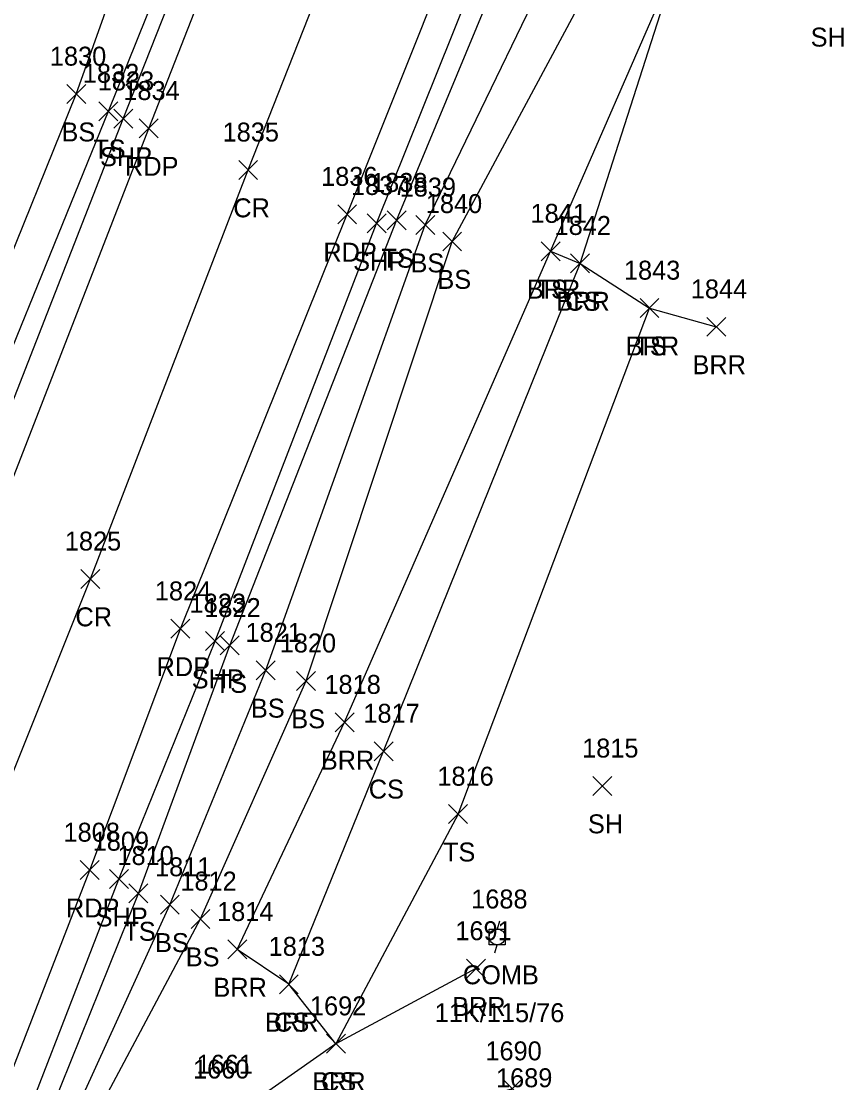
# Model space of a CAD drawing. Extents: x 1554917 to 1555870, y 813367 to 816333.
# Drawn here: x 1555289.9 to 1555376.7, y 814161.6 to 814273.6 of the extents above; entities that cross this region are included whole.
import ezdxf

# ---------------------------------------------------------------- set-up
doc = ezdxf.new("R2010")
doc.units = 0
for name, color, linetype in [('C_I', 7, 'Continuous'), ('L_A', 7, 'Continuous'), ('L_I', 7, 'Continuous'), ('L_TIC', 7, 'Continuous'), ('LABL', 7, 'Continuous'), ('LELB', 7, 'Continuous'), ('P_A', 7, 'Continuous'), ('P_I', 7, 'Continuous'), ('P_TIC', 7, 'Continuous'), ('PET', 7, 'Continuous'), ('PRC', 7, 'Continuous'), ('PSP', 7, 'Continuous'), ('R_I', 7, 'Continuous'), ('U_A', 7, 'Continuous'), ('U_C', 7, 'Continuous'), ('U_I', 7, 'Continuous'), ('UP', 7, 'Continuous')]:
    doc.layers.add(name, color=color, linetype=linetype)

msp = doc.modelspace()

# ---------------------------------------------------------------- linework, layer by layer
at = {"layer": 'L_TIC'}
for points in [[(1555294.68, 814264.95), (1555296.68, 814266.95)], [(1555296.68, 814264.95), (1555294.68, 814266.95)], [(1555298.07, 814263.14), (1555300.07, 814265.14)], [(1555300.07, 814263.14), (1555298.07, 814265.14)], [(1555328.49, 814251.62), (1555330.49, 814253.62)], [(1555330.49, 814251.62), (1555328.49, 814253.62)], [(1555331.52, 814251.13), (1555333.52, 814253.13)], [(1555333.52, 814251.13), (1555331.52, 814253.13)], [(1555334.36, 814249.39), (1555336.36, 814251.39)], [(1555336.36, 814249.39), (1555334.36, 814251.39)], [(1555344.75, 814248.36), (1555346.75, 814250.36)], [(1555346.75, 814248.36), (1555344.75, 814250.36)], [(1555344.75, 814248.36), (1555346.75, 814250.36)], [(1555346.75, 814248.36), (1555344.75, 814250.36)], [(1555347.86, 814247.08), (1555349.86, 814249.08)], [(1555349.86, 814247.08), (1555347.86, 814249.08)], [(1555347.86, 814247.08), (1555349.86, 814249.08)], [(1555349.86, 814247.08), (1555347.86, 814249.08)], [(1555355.19, 814242.36), (1555357.19, 814244.36)], [(1555357.19, 814242.36), (1555355.19, 814244.36)], [(1555355.19, 814242.36), (1555357.19, 814244.36)], [(1555357.19, 814242.36), (1555355.19, 814244.36)], [(1555362.24, 814240.38), (1555364.24, 814242.38)], [(1555364.24, 814240.38), (1555362.24, 814242.38)], [(1555310.89, 814206.75), (1555312.89, 814208.75)], [(1555312.89, 814206.75), (1555310.89, 814208.75)], [(1555314.68, 814204.13), (1555316.68, 814206.13)], [(1555316.68, 814204.13), (1555314.68, 814206.13)], [(1555318.94, 814203.01), (1555320.94, 814205.01)], [(1555320.94, 814203.01), (1555318.94, 814205.01)], [(1555323.01, 814198.64), (1555325.01, 814200.64)], [(1555325.01, 814198.64), (1555323.01, 814200.64)], [(1555327.12, 814195.59), (1555329.12, 814197.59)], [(1555329.12, 814195.59), (1555327.12, 814197.59)], [(1555350.21, 814191.92), (1555352.21, 814193.92)], [(1555352.21, 814191.92), (1555350.21, 814193.92)], [(1555334.98, 814188.95), (1555336.98, 814190.95)], [(1555336.98, 814188.95), (1555334.98, 814190.95)], [(1555301.24, 814180.58), (1555303.24, 814182.58)], [(1555303.24, 814180.58), (1555301.24, 814182.58)], [(1555304.56, 814179.39), (1555306.56, 814181.39)], [(1555306.56, 814179.39), (1555304.56, 814181.39)], [(1555307.8, 814177.88), (1555309.8, 814179.88)], [(1555309.8, 814177.88), (1555307.8, 814179.88)], [(1555311.68, 814174.67), (1555313.68, 814176.67)], [(1555313.68, 814174.67), (1555311.68, 814176.67)], [(1555336.87, 814172.64), (1555338.87, 814174.64)], [(1555338.87, 814172.64), (1555336.87, 814174.64)], [(1555317.12, 814170.99), (1555319.12, 814172.99)], [(1555319.12, 814170.99), (1555317.12, 814172.99)], [(1555317.12, 814170.99), (1555319.12, 814172.99)], [(1555319.12, 814170.99), (1555317.12, 814172.99)], [(1555322.09, 814164.71), (1555324.09, 814166.71)], [(1555324.09, 814164.71), (1555322.09, 814166.71)], [(1555322.09, 814164.71), (1555324.09, 814166.71)], [(1555324.09, 814164.71), (1555322.09, 814166.71)], [(1555340.7, 814159.96), (1555342.7, 814161.96)], [(1555342.7, 814159.96), (1555340.7, 814161.96)]]:
    msp.add_lwpolyline(points, dxfattribs=at)
at = {"layer": 'LABL'}
msp.add_lwpolyline([(1555337.87, 814173.64), (1555323.09, 814165.71), (1555318.12, 814171.99), (1555312.68, 814175.67), (1555324.01, 814199.64), (1555345.75, 814249.36), (1555348.86, 814248.08), (1555356.19, 814243.36), (1555363.24, 814241.38)], dxfattribs=at)
at = {"layer": 'LELB'}
for points in [[(1555296.24, 814366.8), (1555290.72, 814331.05), (1555289.09, 814310.79), (1555285.93, 814285.82), (1555277.62, 814260.54), (1555271.26, 814235.38), (1555263.98, 814210.11), (1555261.73, 814196.47), (1555265.94, 814194.83), (1555271.45, 814194.97), (1555281.92, 814221.99), (1555299.07, 814264.14), (1555315.35, 814304.52), (1555325.95, 814332.17)], [(1555341.7, 814160.96), (1555323.87, 814155.26), (1555306.26, 814148.83), (1555294.41, 814144.19), (1555291.45, 814143.72), (1555289.04, 814144.16), (1555287.98, 814146.11), (1555302.24, 814181.58), (1555311.89, 814207.75), (1555329.49, 814252.62), (1555345.31, 814290.75), (1555356.6, 814322.62)], [(1555291.01, 814145.47), (1555290.78, 814144.99), (1555289.94, 814146.12), (1555305.56, 814180.39), (1555315.68, 814205.13), (1555332.52, 814252.13), (1555349.73, 814287.71), (1555359.86, 814320.99)], [(1555291.01, 814145.47), (1555308.8, 814178.88), (1555319.94, 814204.01), (1555335.36, 814250.39), (1555355.88, 814288.58), (1555362.55, 814319.62)], [(1555318.12, 814171.99), (1555328.12, 814196.59), (1555348.86, 814248.08), (1555359.2, 814280.31), (1555369.32, 814316.68)], [(1555288.75, 814285.24), (1555281.61, 814259.69), (1555272.83, 814234.77), (1555266.17, 814210.24), (1555264.49, 814198.29), (1555266.03, 814197.26), (1555266.73, 814197.03), (1555278.25, 814222.88), (1555295.68, 814265.95), (1555300.44, 814279.31)], [(1555345.75, 814249.36), (1555359.2, 814280.31)], [(1555335.98, 814189.95), (1555356.19, 814243.36)], [(1555335.98, 814189.95), (1555323.09, 814165.71)], [(1555323.09, 814165.71), (1555304.67, 814152.78), (1555294.41, 814144.19)]]:
    msp.add_lwpolyline(points, dxfattribs=at)
at = {"layer": 'P_TIC'}
for points in [[(1555299.65, 814262.34), (1555301.65, 814264.34)], [(1555301.65, 814262.34), (1555299.65, 814264.34)], [(1555302.34, 814261.32), (1555304.34, 814263.32)], [(1555304.34, 814261.32), (1555302.34, 814263.32)], [(1555312.83, 814256.94), (1555314.83, 814258.94)], [(1555314.83, 814256.94), (1555312.83, 814258.94)], [(1555323.28, 814252.26), (1555325.28, 814254.26)], [(1555325.28, 814252.26), (1555323.28, 814254.26)], [(1555326.38, 814251.3), (1555328.38, 814253.3)], [(1555328.38, 814251.3), (1555326.38, 814253.3)], [(1555296.17, 814213.77), (1555298.17, 814215.77)], [(1555298.17, 814213.77), (1555296.17, 814215.77)], [(1555305.67, 814208.51), (1555307.67, 814210.51)], [(1555307.67, 814208.51), (1555305.67, 814210.51)], [(1555309.34, 814207.22), (1555311.34, 814209.22)], [(1555311.34, 814207.22), (1555309.34, 814209.22)], [(1555296.11, 814183.04), (1555298.11, 814185.04)], [(1555298.11, 814183.04), (1555296.11, 814185.04)], [(1555299.19, 814182.09), (1555301.19, 814184.09)], [(1555301.19, 814182.09), (1555299.19, 814184.09)]]:
    msp.add_lwpolyline(points, dxfattribs=at)
at = {"layer": 'PET'}
for points in [[(1555161.36, 813900.53), (1555183.5, 813956.99), (1555189.63, 813971.7), (1555196.36, 813987.75), (1555203.89, 814008), (1555206.01, 814012.95), (1555218.07, 814043.52), (1555227.32, 814068.19), (1555240.79, 814103.21), (1555254.41, 814137.22), (1555273.72, 814186.43), (1555286.72, 814219.57), (1555303.34, 814262.32), (1555319.11, 814302.56), (1555330.34, 814331.97)], [(1555182.57, 813892.25), (1555203.7, 813945.01), (1555216.85, 813978.34), (1555228.72, 814008.85), (1555239.47, 814035.47), (1555248.64, 814059.88), (1555262.92, 814096.01), (1555276.68, 814131.3), (1555286.36, 814156.33), (1555297.11, 814184.04), (1555306.67, 814209.51), (1555324.28, 814253.26), (1555340.35, 814293.54), (1555352.6, 814325.05)]]:
    msp.add_lwpolyline(points, dxfattribs=at)
at = {"layer": 'PRC'}
msp.add_lwpolyline([(1554976.76, 813382.18), (1554992.84, 813427.9), (1555014.07, 813486.01), (1555030.62, 813532.31), (1555046.37, 813573.08), (1555064.69, 813621.19), (1555082.41, 813667.53), (1555112.1, 813744.1), (1555110.69, 813739.79), (1555136.16, 813805.74), (1555152.52, 813846.93), (1555172.03, 813896.18), (1555193.96, 813951.2), (1555206.37, 813983.4), (1555218.13, 814013.22), (1555228.65, 814039.26), (1555237.93, 814064.31), (1555252.22, 814099.76), (1555265.8, 814135.89), (1555275.26, 814160.09), (1555297.17, 814214.77), (1555313.83, 814257.94), (1555329.72, 814298.26), (1555342.03, 814329.92)], dxfattribs=at)
at = {"layer": 'PSP'}
for points in [[(1555160.79, 813906.47), (1555173.05, 813937.33), (1555179.42, 813953.63), (1555181.24, 813957.84), (1555186.72, 813973.16), (1555194.02, 813990.9), (1555204.38, 814016.29), (1555205.03, 814017.75), (1555215.29, 814044.5), (1555224.66, 814068.93), (1555238.68, 814103.48), (1555248.96, 814130.73), (1555261.62, 814162.67), (1555270.99, 814187.05), (1555283.98, 814220.8), (1555300.65, 814263.34), (1555316.51, 814303.51), (1555327.36, 814331.38)], [(1555197.67, 813922.42), (1555211.91, 813956.86), (1555220.23, 813977.15), (1555231.8, 814008.2), (1555242.48, 814034.48), (1555251.86, 814058.97), (1555266.04, 814094.8), (1555272.79, 814112.73), (1555286.23, 814147.2), (1555300.19, 814183.09), (1555310.34, 814208.22), (1555327.38, 814252.3), (1555343.49, 814292.44), (1555355.29, 814323.57)]]:
    msp.add_lwpolyline(points, dxfattribs=at)
at = {"layer": 'UP'}
for p, q in [((1555340.36, 814178.65), (1555340.11, 814177.82)), ((1555339.28, 814176.15), (1555339.28, 814177.82)), ((1555339.28, 814177.82), (1555340.94, 814177.82)), ((1555340.11, 814176.99), (1555340.11, 814176.99)), ((1555340.94, 814177.82), (1555340.94, 814176.15)), ((1555340.94, 814176.15), (1555339.28, 814176.15)), ((1555339.86, 814175.32), (1555340.11, 814176.15))]:
    msp.add_line(p, q, dxfattribs=at)
msp.add_circle((1555340.11, 814176.99), 0.833, dxfattribs=at)

# ---------------------------------------------------------------- texts
at = {"layer": 'C_I'}
msp.add_text('1661', height=2, dxfattribs=at).set_placement((1555308.38, 814162.55))
at = {"layer": 'L_A'}
for s, p in [('SH', (1555373.2, 814270.96)), ('BS', (1555294.12, 814260.95)), ('TS', (1555297.48, 814259.14)), ('TS', (1555327.9, 814247.62)), ('BS', (1555330.96, 814247.13)), ('BS', (1555333.8, 814245.39)), ('BRR', (1555343.24, 814244.36)), ('TS', (1555344.16, 814244.36)), ('BRR', (1555346.35, 814243.08)), ('CS', (1555347.3, 814243.08)), ('BRR', (1555353.68, 814238.36)), ('TS', (1555354.6, 814238.36)), ('BRR', (1555360.73, 814236.38)), ('TS', (1555310.3, 814202.75)), ('BS', (1555314.12, 814200.13)), ('BS', (1555318.38, 814199.01)), ('BRR', (1555321.5, 814194.64)), ('CS', (1555326.56, 814191.59)), ('SH', (1555349.69, 814187.92)), ('TS', (1555334.39, 814184.95)), ('TS', (1555300.65, 814176.58)), ('BS', (1555304, 814175.39)), ('BS', (1555307.24, 814173.88)), ('BRR', (1555310.16, 814170.67)), ('BRR', (1555335.36, 814168.64)), ('BRR', (1555315.61, 814166.99)), ('CS', (1555316.56, 814166.99)), ('BRR', (1555320.58, 814160.71)), ('CS', (1555321.53, 814160.71))]:
    msp.add_text(s, height=2, dxfattribs=at).set_placement(p)
at = {"layer": 'L_I'}
for s, p in [('1830', (1555292.9, 814268.95)), ('1832', (1555296.38, 814267.14)), ('1838', (1555326.8, 814255.62)), ('1839', (1555329.82, 814255.13)), ('1840', (1555332.58, 814253.39)), ('1841', (1555343.63, 814252.36)), ('1841', (1555343.63, 814252.36)), ('1842', (1555346.17, 814251.08)), ('1842', (1555346.17, 814251.08)), ('1843', (1555353.49, 814246.36)), ('1843', (1555353.49, 814246.36)), ('1844', (1555360.55, 814244.38)), ('1822', (1555309.2, 814210.75)), ('1821', (1555313.55, 814208.13)), ('1820', (1555317.16, 814207.01)), ('1818', (1555321.88, 814202.64)), ('1817', (1555325.99, 814199.59)), ('1815', (1555349.08, 814195.92)), ('1816', (1555333.8, 814192.95)), ('1810', (1555300.03, 814184.58)), ('1811', (1555304, 814183.39)), ('1812', (1555306.67, 814181.88)), ('1814', (1555310.55, 814178.67)), ('1691', (1555335.7, 814176.64)), ('1813', (1555315.99, 814174.99)), ('1813', (1555315.99, 814174.99)), ('1692', (1555320.35, 814168.71)), ('1692', (1555320.35, 814168.71)), ('1690', (1555338.87, 814163.96)), ('1660', (1555308.01, 814162.04))]:
    msp.add_text(s, height=2, dxfattribs=at).set_placement(p)
at = {"layer": 'P_A'}
for s, p in [('SHP', (1555298.19, 814258.34)), ('RDP', (1555300.83, 814257.32)), ('CR', (1555312.26, 814252.94)), ('RDP', (1555321.77, 814248.26)), ('SHP', (1555324.91, 814247.3)), ('CR', (1555295.6, 814209.77)), ('RDP', (1555304.16, 814204.51)), ('SHP', (1555307.87, 814203.22)), ('RDP', (1555294.6, 814179.04)), ('SHP', (1555297.73, 814178.09))]:
    msp.add_text(s, height=2, dxfattribs=at).set_placement(p)
at = {"layer": 'P_I'}
for s, p in [('1833', (1555297.96, 814266.34)), ('1834', (1555300.65, 814265.32)), ('1835', (1555311.13, 814260.94)), ('1836', (1555321.53, 814256.26)), ('1837', (1555324.68, 814255.3)), ('1825', (1555294.48, 814217.77)), ('1824', (1555303.98, 814212.51)), ('1823', (1555307.64, 814211.22)), ('1808', (1555294.34, 814187.04)), ('1809', (1555297.42, 814186.09))]:
    msp.add_text(s, height=2, dxfattribs=at).set_placement(p)
at = {"layer": 'R_I'}
msp.add_text('1689', height=2, dxfattribs=at).set_placement((1555339.99, 814161.12))
at = {"layer": 'U_A'}
msp.add_text('COMB', height=2, dxfattribs=at).set_placement((1555336.49, 814171.99))
at = {"layer": 'U_C'}
msp.add_text('11K/115/76', height=2, dxfattribs=at).set_placement((1555333.52, 814167.99))
at = {"layer": 'U_I'}
msp.add_text('1688', height=2, dxfattribs=at).set_placement((1555337.37, 814179.99))

doc.saveas('drawing.dxf')
